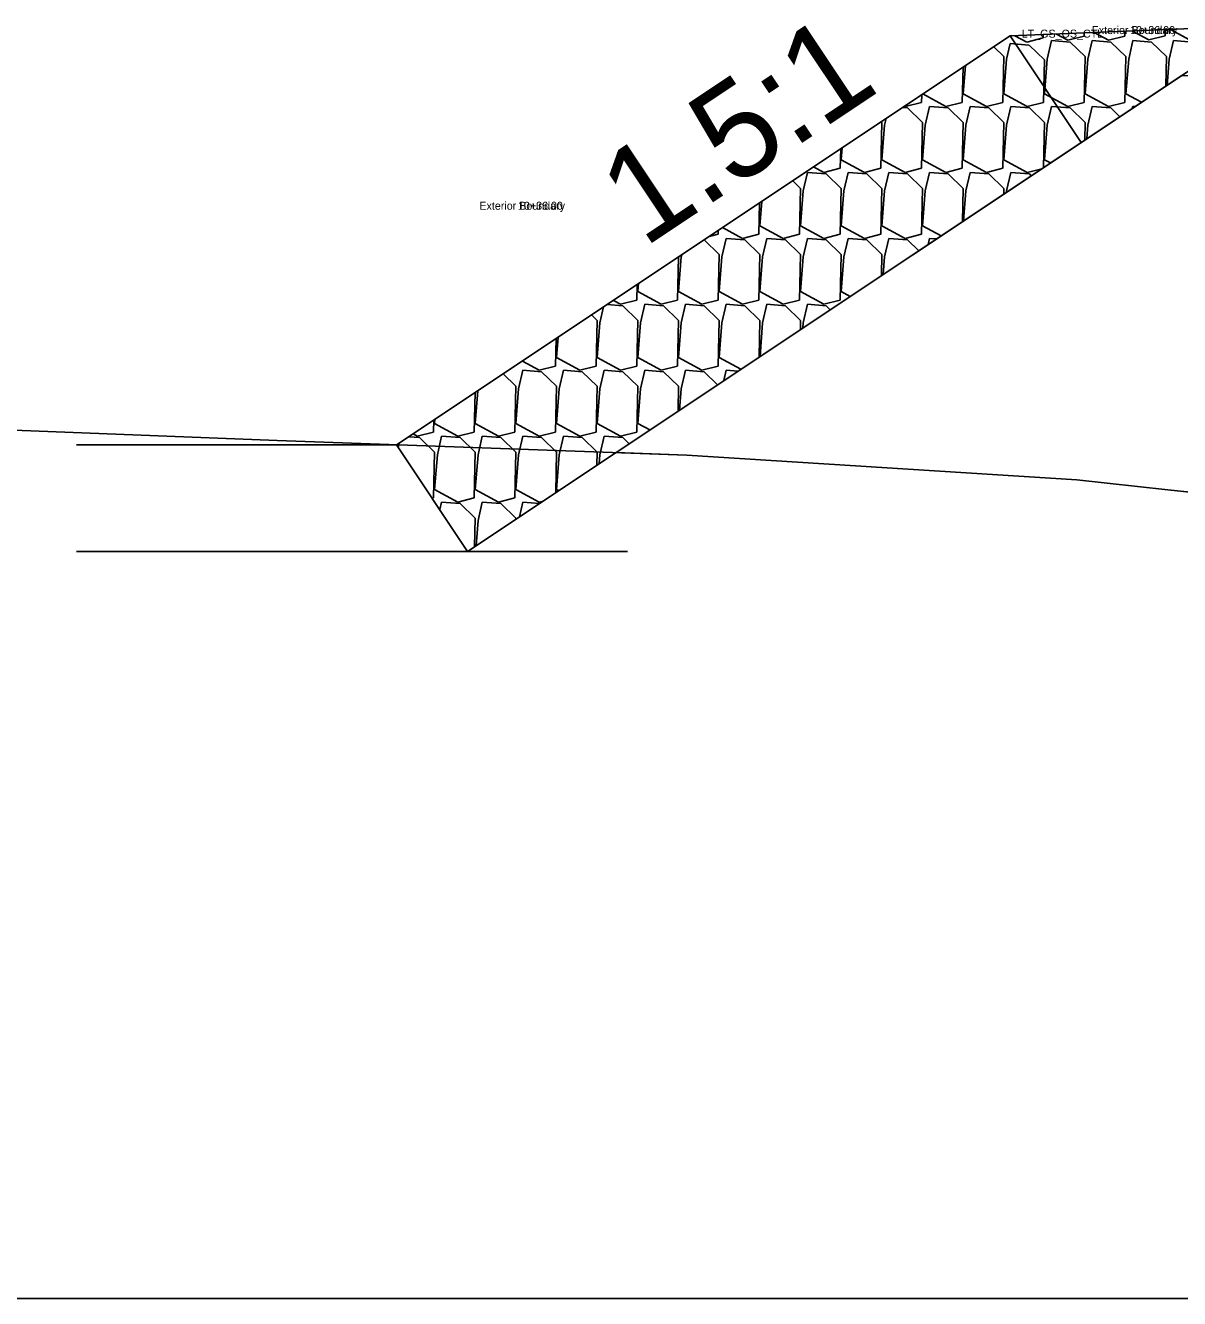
# Model space of a CAD drawing. Extents: x -26 to 2903, y -10 to 63.
# Drawn here: x 116.28 to 134.3, y 0 to 19.88 of the extents above; entities that cross this region are included whole.
import ezdxf

# ---------------------------------------------------------------- set-up
doc = ezdxf.new("R2010")
doc.units = 0
for name, color, linetype in [('Exist Cross Section Cell', 7, 'Continuous'), ('Exist XS Ground Line', 7, 'Continuous'), ('Prop CMT Slope Grass', 7, 'Continuous'), ('Prop XS Earthwork Shape', 7, 'Continuous'), ('Prop XS SE Text', 7, 'Continuous'), ('Prop XS Side Slope Text', 7, 'Continuous'), ('Scratch_Level_0', 7, 'Continuous'), ('Scratch_Level_3', 7, 'Continuous')]:
    doc.layers.add(name, color=color, linetype=linetype)

msp = doc.modelspace()

# ---------------------------------------------------------------- linework, layer by layer
at = {"layer": 'Exist Cross Section Cell'}
msp.add_line((0, 0), (150, 0), dxfattribs=at)
at = {"layer": 'Exist XS Ground Line'}
for p, q in [((115.483, 13.585), (120.213, 13.399)), ((120.213, 13.399), (126.607, 13.172)), ((126.607, 13.172), (132.699, 12.782)), ((132.699, 12.782), (134.115, 12.628)), ((134.115, 12.628), (135.818, 12.45))]:
    msp.add_line(p, q, dxfattribs=at)
at = {"layer": 'Prop CMT Slope Grass'}
msp.add_line((135.49, 19.87), (125.502, 13.212), dxfattribs=at)
at = {"layer": 'Prop XS Earthwork Shape'}
msp.add_lwpolyline([(163.445, 18.518), (149.987, 18.787), (136.595, 19.055), (134.335, 19.1), (125.502, 13.212), (126.607, 13.172), (132.699, 12.782), (134.115, 12.628), (135.818, 12.45), (138.979, 12.096), (141.766, 11.887), (144.767, 11.587), (146.165, 11.415), (147.067, 11.271), (148.767, 11.089), (150, 10.856), (151.604, 10.554), (152.413, 10.398), (153.029, 10.26), (156.738, 9.226), (158.457, 8.712), (171.493, 5), (186.718, 5), (166.535, 18.456)], close=True, dxfattribs=at)
at = {"layer": 'Prop XS SE Text'}
for p, q in [((131.656, 19.717), (122.075, 13.331)), ((135.49, 19.87), (131.656, 19.717)), ((131.915, 19.619), (131.729, 19.72)), ((132.171, 19.684), (131.915, 19.619)), ((132.172, 19.738), (132.171, 19.685)), ((132.554, 19.649), (132.377, 19.746)), ((132.81, 19.714), (132.554, 19.649)), ((132.812, 19.763), (132.811, 19.715)), ((133.189, 19.649), (132.968, 19.77)), ((133.445, 19.714), (133.189, 19.649)), ((133.448, 19.789), (133.446, 19.715)), ((133.82, 19.655), (133.565, 19.793)), ((134.076, 19.719), (133.82, 19.655)), ((134.078, 19.814), (134.076, 19.719)), ((134.455, 19.655), (134.157, 19.817)), ((131.399, 19.547), (131.558, 19.393)), ((131.601, 19.355), (131.654, 19.597)), ((131.657, 19.597), (131.949, 19.574)), ((131.954, 19.571), (132.19, 19.343)), ((132.236, 19.355), (132.299, 19.644)), ((132.299, 19.644), (132.592, 19.621)), ((132.592, 19.621), (132.828, 19.393)), ((132.871, 19.355), (132.934, 19.644)), ((132.934, 19.644), (133.227, 19.621)), ((133.227, 19.621), (133.463, 19.393)), ((133.506, 19.355), (133.569, 19.644)), ((133.569, 19.644), (133.862, 19.621)), ((133.862, 19.621), (134.098, 19.393)), ((134.14, 19.355), (134.204, 19.644)), ((134.204, 19.644), (134.497, 19.621)), ((131.558, 19.393), (131.543, 18.679)), ((131.558, 18.813), (131.601, 19.355)), ((132.192, 19.341), (132.178, 18.679)), ((132.193, 18.813), (132.236, 19.355)), ((132.828, 19.393), (132.813, 18.679)), ((132.828, 18.813), (132.871, 19.355)), ((133.463, 19.393), (133.448, 18.679)), ((133.463, 18.813), (133.506, 19.355)), ((134.098, 19.393), (134.088, 18.93)), ((134.108, 18.943), (134.14, 19.355)), ((130.92, 19.227), (130.908, 18.679)), ((130.923, 18.813), (130.958, 19.252)), ((130.275, 18.797), (130.273, 18.679)), ((130.652, 18.615), (130.294, 18.81)), ((131.287, 18.615), (130.923, 18.813)), ((131.922, 18.615), (131.558, 18.813)), ((132.557, 18.615), (132.193, 18.813)), ((133.192, 18.615), (132.828, 18.813)), ((133.706, 18.68), (133.463, 18.813)), ((129.976, 18.598), (130.052, 18.592)), ((130.017, 18.615), (130.008, 18.619)), ((130.273, 18.679), (130.017, 18.615)), ((130.052, 18.592), (130.288, 18.363)), ((130.331, 18.325), (130.394, 18.615)), ((130.394, 18.615), (130.687, 18.592)), ((130.908, 18.679), (130.652, 18.615)), ((130.687, 18.592), (130.923, 18.363)), ((130.966, 18.325), (131.029, 18.615)), ((131.029, 18.615), (131.322, 18.592)), ((131.543, 18.679), (131.287, 18.615)), ((131.322, 18.592), (131.558, 18.363)), ((131.601, 18.325), (131.664, 18.615)), ((131.664, 18.615), (131.957, 18.592)), ((132.178, 18.679), (131.922, 18.615)), ((131.957, 18.592), (132.193, 18.363)), ((132.236, 18.325), (132.299, 18.615)), ((132.299, 18.615), (132.592, 18.592)), ((132.813, 18.679), (132.557, 18.615)), ((132.592, 18.592), (132.828, 18.363)), ((132.871, 18.325), (132.934, 18.615)), ((132.934, 18.615), (133.227, 18.592)), ((133.448, 18.679), (133.192, 18.615)), ((133.227, 18.592), (133.368, 18.455)), ((133.563, 18.585), (133.569, 18.615)), ((133.569, 18.615), (133.603, 18.612)), ((129.653, 18.363), (129.638, 17.65)), ((129.641, 18.375), (129.653, 18.363)), ((129.653, 17.783), (129.696, 18.325)), ((129.696, 18.325), (129.718, 18.426)), ((130.288, 18.363), (130.273, 17.65)), ((130.288, 17.783), (130.331, 18.325)), ((130.923, 18.363), (130.908, 17.65)), ((130.923, 17.783), (130.966, 18.325)), ((131.558, 18.363), (131.543, 17.65)), ((131.558, 17.783), (131.601, 18.325)), ((132.193, 18.363), (132.178, 17.662)), ((132.193, 17.783), (132.236, 18.325)), ((132.828, 18.363), (132.822, 18.091)), ((132.854, 18.113), (132.871, 18.325)), ((129.01, 17.953), (129.003, 17.65)), ((129.018, 17.783), (129.033, 17.969)), ((129.382, 17.585), (129.018, 17.783)), ((130.017, 17.585), (129.653, 17.783)), ((130.652, 17.585), (130.288, 17.783)), ((131.287, 17.585), (130.923, 17.783)), ((131.922, 17.585), (131.558, 17.783)), ((132.285, 17.733), (132.193, 17.783)), ((128.426, 17.295), (128.49, 17.585)), ((128.49, 17.585), (128.782, 17.562)), ((128.747, 17.585), (128.587, 17.672)), ((129.003, 17.65), (128.747, 17.585)), ((128.782, 17.562), (129.018, 17.333)), ((129.061, 17.295), (129.124, 17.585)), ((129.124, 17.585), (129.417, 17.562)), ((129.638, 17.65), (129.382, 17.585)), ((129.417, 17.562), (129.653, 17.333)), ((129.696, 17.295), (129.759, 17.585)), ((129.759, 17.585), (130.052, 17.562)), ((130.273, 17.65), (130.017, 17.585)), ((130.052, 17.562), (130.288, 17.333)), ((130.331, 17.295), (130.394, 17.585)), ((130.394, 17.585), (130.687, 17.562)), ((130.908, 17.65), (130.652, 17.585)), ((130.687, 17.562), (130.923, 17.333)), ((130.966, 17.295), (131.029, 17.585)), ((131.029, 17.585), (131.322, 17.562)), ((131.543, 17.65), (131.287, 17.585)), ((131.322, 17.562), (131.558, 17.333)), ((131.601, 17.295), (131.664, 17.585)), ((131.664, 17.585), (131.957, 17.562)), ((132.148, 17.642), (131.922, 17.585)), ((131.957, 17.562), (131.986, 17.534)), ((128.26, 17.453), (128.383, 17.333)), ((128.383, 17.333), (128.368, 16.62)), ((128.383, 16.753), (128.426, 17.295)), ((129.018, 17.333), (129.003, 16.62)), ((129.018, 16.753), (129.061, 17.295)), ((129.653, 17.333), (129.638, 16.62)), ((129.653, 16.753), (129.696, 17.295)), ((130.288, 17.333), (130.273, 16.62)), ((130.288, 16.753), (130.331, 17.295)), ((130.923, 17.333), (130.912, 16.818)), ((130.929, 16.829), (130.966, 17.295)), ((131.558, 17.333), (131.556, 17.247)), ((131.599, 17.276), (131.601, 17.295)), ((127.744, 17.109), (127.733, 16.62)), ((127.748, 16.753), (127.778, 17.133)), ((127.477, 16.555), (127.166, 16.725)), ((128.112, 16.555), (127.748, 16.753)), ((128.747, 16.555), (128.383, 16.753)), ((129.382, 16.555), (129.018, 16.753)), ((130.017, 16.555), (129.653, 16.753)), ((130.578, 16.596), (130.288, 16.753)), ((126.878, 16.532), (127.114, 16.304)), ((127.098, 16.62), (126.955, 16.584)), ((127.099, 16.68), (127.098, 16.62)), ((127.156, 16.266), (127.22, 16.555)), ((127.22, 16.555), (127.513, 16.532)), ((127.733, 16.62), (127.477, 16.555)), ((127.513, 16.532), (127.748, 16.304)), ((127.791, 16.266), (127.855, 16.555)), ((127.855, 16.555), (128.147, 16.532)), ((128.368, 16.62), (128.112, 16.555)), ((128.147, 16.532), (128.383, 16.304)), ((128.426, 16.266), (128.49, 16.555)), ((128.49, 16.555), (128.782, 16.532)), ((129.003, 16.62), (128.747, 16.555)), ((128.782, 16.532), (129.018, 16.304)), ((129.061, 16.266), (129.124, 16.555)), ((129.124, 16.555), (129.417, 16.532)), ((129.638, 16.62), (129.382, 16.555)), ((129.417, 16.532), (129.653, 16.304)), ((129.696, 16.266), (129.759, 16.555)), ((129.759, 16.555), (130.052, 16.532)), ((130.273, 16.62), (130.017, 16.555)), ((130.052, 16.532), (130.228, 16.362)), ((130.373, 16.459), (130.394, 16.555)), ((130.394, 16.555), (130.505, 16.547)), ((127.114, 16.304), (127.098, 15.59)), ((127.748, 16.304), (127.733, 15.59)), ((128.383, 16.304), (128.368, 15.59)), ((129.018, 16.304), (129.003, 15.59)), ((129.653, 16.304), (129.646, 15.974)), ((126.478, 16.266), (126.463, 15.59)), ((126.479, 15.724), (126.521, 16.266)), ((126.521, 16.266), (126.529, 16.299)), ((127.114, 15.724), (127.156, 16.266)), ((127.748, 15.724), (127.791, 16.266)), ((128.383, 15.724), (128.426, 16.266)), ((129.018, 15.724), (129.061, 16.266)), ((129.674, 15.993), (129.696, 16.266)), ((125.834, 15.836), (125.828, 15.59)), ((125.844, 15.724), (125.854, 15.849)), ((126.207, 15.526), (125.844, 15.724)), ((126.842, 15.526), (126.479, 15.724)), ((127.477, 15.526), (127.114, 15.724)), ((128.112, 15.526), (127.748, 15.724)), ((128.747, 15.526), (128.383, 15.724)), ((129.157, 15.648), (129.018, 15.724)), ((125.363, 15.522), (125.608, 15.503)), ((125.572, 15.526), (125.46, 15.587)), ((125.828, 15.59), (125.572, 15.526)), ((125.886, 15.236), (125.95, 15.526)), ((125.95, 15.526), (126.243, 15.503)), ((126.463, 15.59), (126.207, 15.526)), ((126.521, 15.236), (126.585, 15.526)), ((126.585, 15.526), (126.878, 15.503)), ((127.098, 15.59), (126.842, 15.526)), ((127.156, 15.236), (127.22, 15.526)), ((127.22, 15.526), (127.513, 15.503)), ((127.733, 15.59), (127.477, 15.526)), ((127.791, 15.236), (127.855, 15.526)), ((127.855, 15.526), (128.147, 15.503)), ((128.368, 15.59), (128.112, 15.526)), ((128.426, 15.236), (128.49, 15.526)), ((128.49, 15.526), (128.782, 15.503)), ((129.003, 15.59), (128.747, 15.526)), ((125.12, 15.36), (125.209, 15.274)), ((125.251, 15.236), (125.306, 15.484)), ((125.608, 15.503), (125.844, 15.274)), ((126.243, 15.503), (126.479, 15.274)), ((126.878, 15.503), (127.114, 15.274)), ((127.513, 15.503), (127.748, 15.274)), ((128.147, 15.503), (128.383, 15.274)), ((128.782, 15.503), (128.846, 15.441)), ((125.209, 15.274), (125.193, 14.561)), ((125.209, 14.694), (125.251, 15.236)), ((125.844, 15.274), (125.828, 14.561)), ((125.844, 14.694), (125.886, 15.236)), ((126.479, 15.274), (126.463, 14.561)), ((126.479, 14.694), (126.521, 15.236)), ((127.114, 15.274), (127.098, 14.561)), ((127.114, 14.694), (127.156, 15.236)), ((127.748, 15.274), (127.736, 14.701)), ((127.75, 14.71), (127.791, 15.236)), ((128.383, 15.274), (128.38, 15.13)), ((128.42, 15.157), (128.426, 15.236)), ((124.568, 14.992), (124.558, 14.561)), ((124.574, 14.694), (124.599, 15.013)), ((124.303, 14.496), (124.039, 14.64)), ((124.558, 14.561), (124.303, 14.496)), ((124.938, 14.496), (124.574, 14.694)), ((125.193, 14.561), (124.938, 14.496)), ((125.572, 14.496), (125.209, 14.694)), ((125.828, 14.561), (125.572, 14.496)), ((126.207, 14.496), (125.844, 14.694)), ((126.463, 14.561), (126.207, 14.496)), ((126.842, 14.496), (126.479, 14.694)), ((127.098, 14.561), (126.842, 14.496)), ((127.451, 14.511), (127.114, 14.694)), ((123.738, 14.439), (123.939, 14.245)), ((123.981, 14.207), (124.045, 14.496)), ((124.045, 14.496), (124.338, 14.473)), ((124.338, 14.473), (124.574, 14.245)), ((124.616, 14.207), (124.68, 14.496)), ((124.68, 14.496), (124.973, 14.473)), ((124.973, 14.473), (125.209, 14.245)), ((125.251, 14.207), (125.315, 14.496)), ((125.315, 14.496), (125.608, 14.473)), ((125.608, 14.473), (125.844, 14.245)), ((125.886, 14.207), (125.95, 14.496)), ((125.95, 14.496), (126.243, 14.473)), ((126.243, 14.473), (126.479, 14.245)), ((126.521, 14.207), (126.585, 14.496)), ((126.585, 14.496), (126.878, 14.473)), ((126.878, 14.473), (127.088, 14.269)), ((127.184, 14.333), (127.22, 14.496)), ((127.22, 14.496), (127.407, 14.482)), ((123.302, 14.148), (123.289, 13.531)), ((123.304, 13.665), (123.344, 14.176)), ((123.939, 14.245), (123.923, 13.531)), ((123.939, 13.665), (123.981, 14.207)), ((124.574, 14.245), (124.558, 13.531)), ((124.574, 13.665), (124.616, 14.207)), ((125.209, 14.245), (125.193, 13.531)), ((125.209, 13.665), (125.251, 14.207)), ((125.844, 14.245), (125.828, 13.531)), ((125.844, 13.665), (125.886, 14.207)), ((126.479, 14.245), (126.47, 13.857)), ((126.495, 13.873), (126.521, 14.207)), ((122.658, 13.719), (122.654, 13.531)), ((122.669, 13.665), (122.674, 13.73)), ((122.654, 13.531), (122.398, 13.467)), ((123.033, 13.467), (122.669, 13.665)), ((123.289, 13.531), (123.033, 13.467)), ((123.668, 13.467), (123.304, 13.665)), ((123.923, 13.531), (123.668, 13.467)), ((124.303, 13.467), (123.939, 13.665)), ((124.558, 13.531), (124.303, 13.467)), ((124.938, 13.467), (124.574, 13.665)), ((125.193, 13.531), (124.938, 13.467)), ((125.572, 13.467), (125.209, 13.665)), ((125.828, 13.531), (125.572, 13.467)), ((126.03, 13.563), (125.844, 13.665)), ((122.075, 13.331), (123.185, 11.666)), ((122.102, 13.291), (122.116, 13.358)), ((122.265, 13.457), (122.433, 13.444)), ((122.398, 13.467), (122.333, 13.502)), ((122.433, 13.444), (122.669, 13.215)), ((122.712, 13.177), (122.775, 13.467)), ((122.775, 13.467), (123.068, 13.444)), ((123.068, 13.444), (123.304, 13.215)), ((123.347, 13.177), (123.41, 13.467)), ((123.41, 13.467), (123.703, 13.444)), ((123.703, 13.444), (123.939, 13.215)), ((123.981, 13.177), (124.045, 13.467)), ((124.045, 13.467), (124.338, 13.444)), ((124.338, 13.444), (124.574, 13.215)), ((124.616, 13.177), (124.68, 13.467)), ((124.68, 13.467), (124.973, 13.444)), ((124.973, 13.444), (125.209, 13.215)), ((125.251, 13.177), (125.315, 13.467)), ((125.315, 13.467), (125.608, 13.444)), ((125.608, 13.444), (125.707, 13.348)), ((122.669, 13.215), (122.654, 12.502)), ((122.669, 12.635), (122.712, 13.177)), ((125.502, 13.212), (123.185, 11.666)), ((123.304, 13.215), (123.289, 12.502)), ((123.304, 12.635), (123.347, 13.177)), ((123.939, 13.215), (123.923, 12.502)), ((123.939, 12.635), (123.981, 13.177)), ((124.574, 13.215), (124.56, 12.583)), ((124.574, 12.635), (124.616, 13.177)), ((125.209, 13.215), (125.204, 13.013)), ((125.24, 13.037), (125.251, 13.177)), ((123.033, 12.437), (122.669, 12.635)), ((123.668, 12.437), (123.304, 12.635)), ((124.303, 12.437), (123.939, 12.635)), ((124.609, 12.616), (124.574, 12.635)), ((122.654, 12.502), (122.632, 12.496)), ((122.749, 12.319), (122.775, 12.437)), ((122.775, 12.437), (123.068, 12.414)), ((123.289, 12.502), (123.033, 12.437)), ((123.068, 12.414), (123.304, 12.185)), ((123.347, 12.147), (123.41, 12.437)), ((123.41, 12.437), (123.703, 12.414)), ((123.923, 12.502), (123.668, 12.437)), ((123.703, 12.414), (123.939, 12.185)), ((123.994, 12.206), (124.045, 12.437)), ((124.045, 12.437), (124.309, 12.416)), ((124.364, 12.452), (124.303, 12.437)), ((123.304, 12.185), (123.294, 11.74)), ((123.316, 11.754), (123.347, 12.147)), ((123.939, 12.185), (123.938, 12.169))]:
    msp.add_line(p, q, dxfattribs=at)
at = {"layer": 'Scratch_Level_3'}
for p, q in [((131.656, 19.717), (132.765, 18.053)), ((122.079, 13.333), (117.079, 13.333)), ((125.68, 11.663), (117.079, 11.663))]:
    msp.add_line(p, q, dxfattribs=at)

# ---------------------------------------------------------------- texts
at = {"layer": 'Prop XS Side Slope Text'}
msp.add_text('1.5:1', height=1.5, rotation=33.69, dxfattribs=at).set_placement((125.935, 16.398))
at = {"layer": 'Scratch_Level_0'}
for s, p in [('LT_GS_OS_CTL', (131.836, 19.689)), ('LT_GS_OS_CTL', (131.836, 19.689)), ('Exterior Boundary', (132.928, 19.745)), ('10+36.00', (133.529, 19.745)), ('Exterior Boundary', (123.368, 17.002)), ('10+36.00', (123.97, 17.002))]:
    msp.add_text(s, height=0.125, dxfattribs=at).set_placement(p)

doc.saveas('drawing.dxf')
